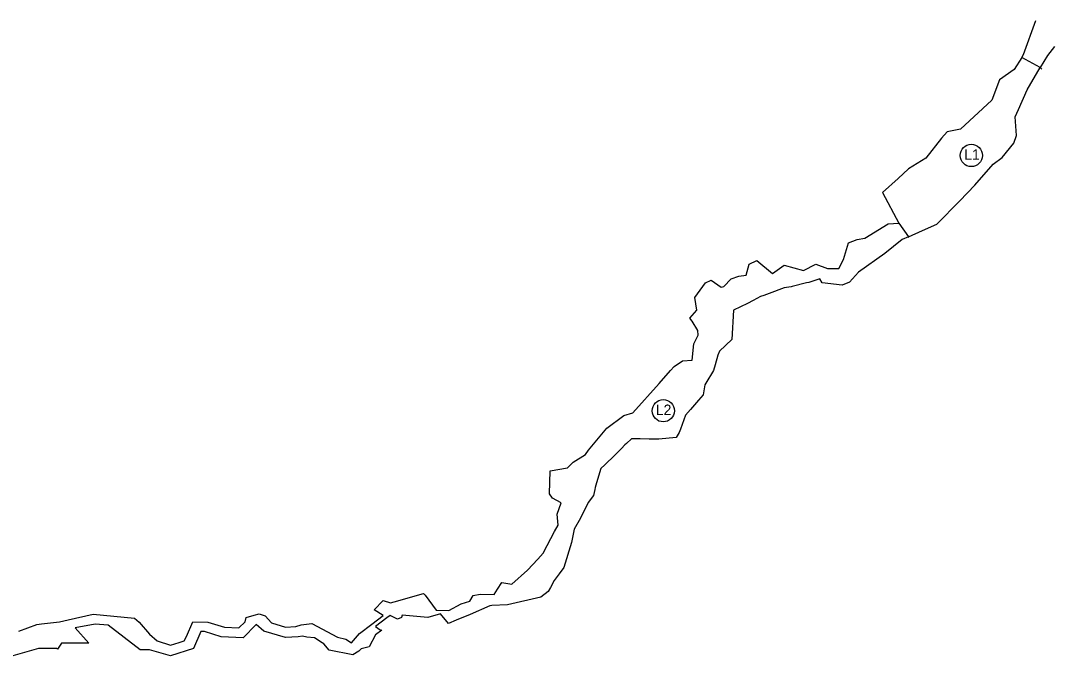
# Model space of a CAD drawing. Extents: x -445081 to -429827, y -1135509 to -1130103.
# Drawn here: x -441644 to -440454, y -1132109 to -1131370 of the extents above; entities that cross this region are included whole.
import ezdxf

# ---------------------------------------------------------------- set-up
doc = ezdxf.new("R2010")
doc.units = 0
for name, color, linetype in [('Vrstva 32', 7, 'Continuous'), ('Vrstva 33', 7, 'Continuous'), ('Vrstva 36', 7, 'Continuous')]:
    doc.layers.add(name, color=color, linetype=linetype)

msp = doc.modelspace()

# ---------------------------------------------------------------- linework, layer by layer
at = {"layer": 'Vrstva 32'}
for points in [[(-440621.7, -1131619.1), (-440605.4, -1131611.9), (-440589, -1131604.6), (-440562.6, -1131577.8), (-440545.4, -1131559.7), (-440524.2, -1131535.8), (-440513.9, -1131527.8), (-440500.5, -1131511.6), (-440497.2, -1131502.5), (-440498.7, -1131481.2), (-440494.9, -1131472.7), (-440485, -1131450.2), (-440469.9, -1131424.5), (-440491.3, -1131412.9), (-440500, -1131426.5), (-440516.8, -1131438.7), (-440525.6, -1131461.9), (-440561.9, -1131495.4), (-440577.2, -1131498.3), (-440583.6, -1131505.7), (-440601.8, -1131528.9), (-440621.5, -1131541.1), (-440633.6, -1131552.1), (-440651.5, -1131568.4), (-440632.8, -1131603.4), (-440621.7, -1131619.1)], [(-440468, -1131426.4), (-440469.9, -1131424.5), (-440491.3, -1131412.9), (-440500, -1131426.5), (-440516.8, -1131438.7), (-440525.6, -1131461.9), (-440561.9, -1131495.4), (-440577.2, -1131498.3), (-440583.6, -1131505.7), (-440601.8, -1131528.9), (-440601.8, -1131528.9), (-440621.5, -1131541.1), (-440633.6, -1131552.1), (-440651.5, -1131568.4), (-440632.8, -1131603.4), (-440621.7, -1131619.1), (-440621.9, -1131620.3)]]:
    msp.add_lwpolyline(points, dxfattribs=at)
at = {"layer": 'Vrstva 33'}
for points in [[(-440491.3, -1131412.9), (-440489.2, -1131409.3), (-440475, -1131370.4)], [(-440453.7, -1131400.1), (-440461.6, -1131410.5), (-440469.9, -1131424.5)], [(-441645.6, -1132073.1), (-441624.9, -1132065.5), (-441619.7, -1132064.9), (-441598.9, -1132062.3), (-441588.8, -1132060.1), (-441560.3, -1132053.8), (-441560.3, -1132053.8), (-441512.7, -1132058.4), (-441507.3, -1132062.7), (-441495.4, -1132076.7), (-441486.6, -1132084.3), (-441471.1, -1132089.4), (-441461.3, -1132086.4), (-441455.2, -1132084.4), (-441452.8, -1132079.2), (-441445.3, -1132062.4), (-441428, -1132062.8), (-441409.1, -1132068.6), (-441392.3, -1132069.2), (-441385.1, -1132062.4), (-441384.1, -1132057.4), (-441374.9, -1132054.9), (-441369, -1132053.3), (-441362.3, -1132055.5), (-441354.7, -1132063.7), (-441338.6, -1132068.6), (-441326.8, -1132067.9), (-441320.6, -1132065.8), (-441308.5, -1132064.4), (-441278.9, -1132080.2), (-441269.4, -1132082.5), (-441262.8, -1132086.8), (-441253.7, -1132075.8), (-441239.5, -1132065), (-441226.4, -1132055.1), (-441236.6, -1132048.6), (-441226.5, -1132037.9), (-441217.9, -1132040.7), (-441213.5, -1132039.4), (-441179.8, -1132029.7), (-441177.8, -1132031.7), (-441165.2, -1132048.9), (-441150.9, -1132049.3), (-441136.7, -1132041.7), (-441126.6, -1132038.8), (-441122.7, -1132032.1), (-441114.6, -1132030.8), (-441098.6, -1132031.1), (-441094.8, -1132025), (-441089.9, -1132017.2), (-441078.3, -1132019), (-441060.2, -1132002.9), (-441048.4, -1131990.2), (-441042.2, -1131983.6), (-441037.4, -1131974.5), (-441028.9, -1131958.4), (-441025, -1131951.1), (-441025.9, -1131938.6), (-441021.4, -1131925.4), (-441031.5, -1131920.1), (-441034.9, -1131915.1), (-441034, -1131888.8), (-441014.3, -1131885), (-441007.7, -1131878.7), (-440993.3, -1131869.9), (-440989.8, -1131864.8), (-440968.7, -1131839.4), (-440949.2, -1131825), (-440938.9, -1131821.9), (-440908.7, -1131788.1), (-440895.4, -1131773.2), (-440891.4, -1131768.6), (-440881.6, -1131762.1), (-440870.8, -1131761.1), (-440868.7, -1131742.5), (-440863.7, -1131732.5), (-440864.1, -1131727.1), (-440870.6, -1131716.2), (-440873.4, -1131713), (-440865.1, -1131703.6), (-440867.4, -1131689.1), (-440855.4, -1131672.4), (-440848.8, -1131669.1), (-440837.4, -1131677.1), (-440834.2, -1131676.6), (-440825.8, -1131667.6), (-440816.9, -1131664.7), (-440808.4, -1131663.5), (-440804.9, -1131650.9), (-440796, -1131646.4), (-440778.3, -1131661.4), (-440764.6, -1131651.8), (-440742.4, -1131658.1), (-440728.1, -1131650.9), (-440714.9, -1131655.9), (-440701.7, -1131655.9), (-440696.3, -1131645.4), (-440690.6, -1131626.1), (-440680.6, -1131622.2), (-440672, -1131620.7), (-440645, -1131604.4), (-440632.8, -1131603.4)], [(-440621.7, -1131619.1), (-440628.8, -1131622.3), (-440649, -1131638.6), (-440679.3, -1131660.1), (-440689.7, -1131671.4), (-440698, -1131674.9), (-440721.1, -1131672.4), (-440723.8, -1131667.7), (-440736.4, -1131671.8), (-440738.9, -1131672.4), (-440755.4, -1131676.6), (-440756.6, -1131676.9), (-440764.7, -1131677.9), (-440782, -1131684.4), (-440788.3, -1131686.7), (-440791.8, -1131688), (-440800.5, -1131692.6), (-440806.8, -1131696), (-440823.2, -1131703.7), (-440824.8, -1131737.5), (-440839.3, -1131751), (-440841.2, -1131755.6), (-440844.3, -1131766.8), (-440846, -1131773.1), (-440854.8, -1131787.8), (-440856, -1131789.8), (-440858.1, -1131801), (-440863.5, -1131807.3), (-440872.7, -1131818), (-440878.2, -1131824.4), (-440884, -1131840.7), (-440885.4, -1131844.5), (-440888.9, -1131850.3), (-440908.9, -1131852.2), (-440920.2, -1131852.2), (-440930.5, -1131851.9), (-440940.4, -1131852), (-440946.3, -1131857.1), (-440948, -1131858.8), (-440952.1, -1131863), (-440959.6, -1131870.7), (-440971, -1131881.6), (-440975.7, -1131886), (-440975.9, -1131886.1), (-440980.9, -1131902.3), (-440982.2, -1131907.9), (-440982.7, -1131910.1), (-440984.3, -1131917.1), (-440990.5, -1131925.2), (-440999.2, -1131943.1), (-441006.5, -1131955.8), (-441009.7, -1131971), (-441018.5, -1132000.1), (-441023.7, -1132007.3), (-441029.6, -1132014.7), (-441033.8, -1132022.8), (-441036.3, -1132027.7), (-441044.8, -1132033.9), (-441083.1, -1132042.9), (-441101.3, -1132043.8), (-441103.5, -1132043.9), (-441126.3, -1132054), (-441142.4, -1132060.6), (-441151, -1132064.2), (-441160.5, -1132053.4), (-441174.9, -1132057.4), (-441204.5, -1132054.6), (-441205.1, -1132057.6), (-441210, -1132059.4), (-441218.3, -1132055.1), (-441222, -1132057.9), (-441235.2, -1132067.9), (-441235.2, -1132067.9), (-441229.8, -1132071.7), (-441228, -1132072.1), (-441235.2, -1132077.6), (-441242.5, -1132091.1), (-441251.6, -1132093.5), (-441254.3, -1132096.3), (-441261.4, -1132100.6), (-441288.3, -1132095.2), (-441294.8, -1132087.9), (-441296.5, -1132086.8), (-441305.4, -1132081), (-441314, -1132080.3), (-441314, -1132080.3), (-441314, -1132080.3), (-441319.2, -1132078.8), (-441319.2, -1132078.8), (-441324.3, -1132079.7), (-441338.8, -1132080.6), (-441363.8, -1132073.4), (-441372.5, -1132065.4), (-441387.6, -1132080.9), (-441412.7, -1132079.8), (-441431.9, -1132073.7), (-441436.2, -1132073.7), (-441444.7, -1132093.2), (-441471.3, -1132101.5), (-441495.2, -1132094.8), (-441506.2, -1132094.7), (-441542.7, -1132066.2), (-441557.9, -1132065.2), (-441580.8, -1132069.2), (-441565.2, -1132086.9), (-441596.6, -1132087.1), (-441596.6, -1132087.1), (-441601, -1132094.1), (-441601, -1132094.1), (-441602.3, -1132093.3), (-441623, -1132093), (-441679.7, -1132109.1)]]:
    msp.add_lwpolyline(points, dxfattribs=at)
at = {"layer": 'Vrstva 36'}
for centre in [(-440549.3, -1131525.6), (-440903.9, -1131819.5)]:
    msp.add_circle(centre, 12.8, dxfattribs=at)

# ---------------------------------------------------------------- texts
for s, p in [('L1', (-440557.4, -1131530.6)), ('L2', (-440912.4, -1131824.4))]:
    msp.add_text(s, height=12, dxfattribs=at).set_placement(p)

doc.saveas('drawing.dxf')
